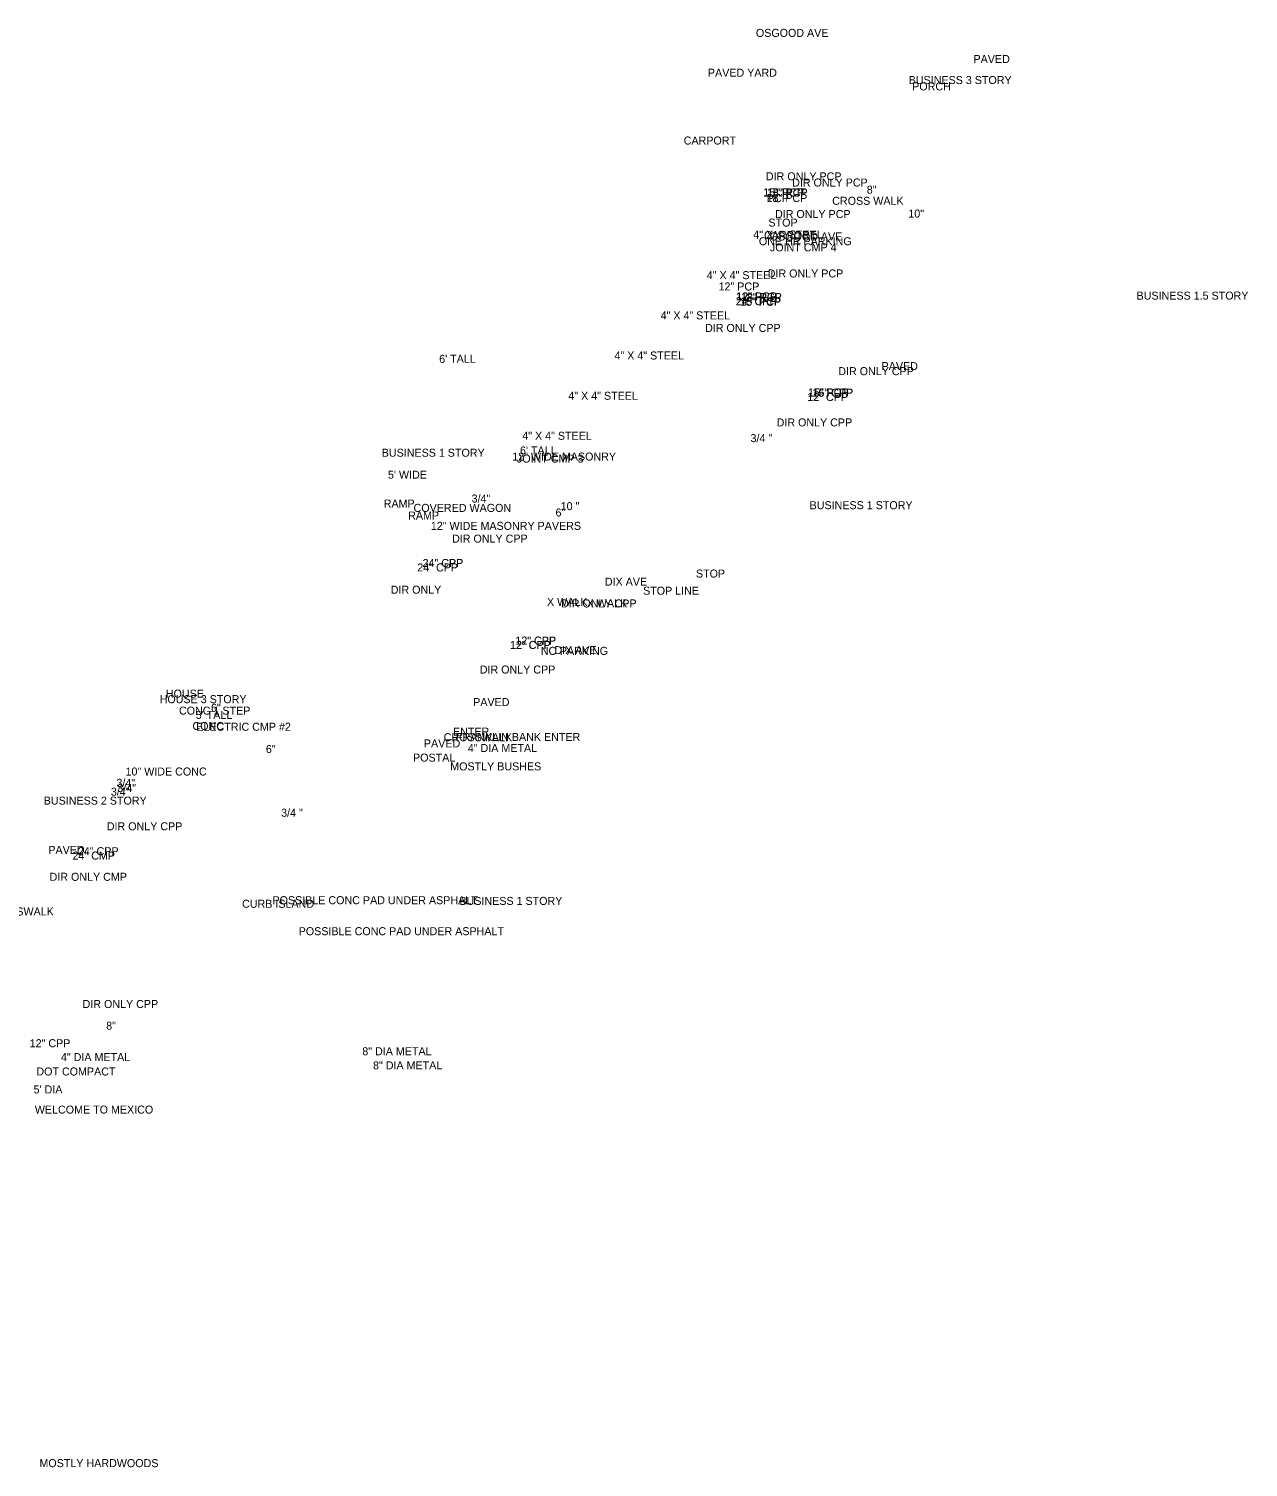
# Model space of a CAD drawing. Extents: x 939002 to 940105, y 627262 to 628202.
# Drawn here: x 939724.4 to 940105, y 627752.3 to 628201.6 of the extents above; entities that cross this region are included whole.
import ezdxf

# ---------------------------------------------------------------- set-up
doc = ezdxf.new("R2010")
doc.units = 0
for name, color, linetype in [('S_Annotation_Label', 7, 'Continuous'), ('S_Buildings', 7, 'Continuous'), ('S_Buildings_Attachments', 7, 'Continuous'), ('S_Buildings_Canopy_Carport', 7, 'Continuous'), ('S_Buildings_SillElevation', 7, 'Continuous'), ('S_Buildings_Steps_Brick', 7, 'Continuous'), ('S_Drainage_Culvert_Top', 7, 'Continuous'), ('S_Drainage_Invert', 7, 'Continuous'), ('S_Fencing_ChainLink', 7, 'Continuous'), ('S_Fencing_Picket', 7, 'Continuous'), ('S_Ground_LevelString', 7, 'Continuous'), ('S_Property_ConcPad', 7, 'Continuous'), ('S_Property_Mailbox', 7, 'Continuous'), ('S_Property_Walkways', 7, 'Continuous'), ('S_RetWall_Top', 7, 'Continuous'), ('S_Roadway_Centerline', 7, 'Continuous'), ('S_Roadway_Edge_Pavement', 7, 'Continuous'), ('S_Roadway_Sidewalks', 7, 'Continuous'), ('S_Traffic_Post_Conc', 7, 'Continuous'), ('S_Traffic_Sign_DoublePost', 7, 'Continuous'), ('S_Traffic_Sign_SinglePost', 7, 'Continuous'), ('S_Trees_Bush', 7, 'Continuous'), ('S_Trees_Bush_Line', 7, 'Continuous'), ('S_Trees_HedgeLine', 7, 'Continuous'), ('S_Trees_TreeLine', 7, 'Continuous'), ('S_Utilities_Pole_Power', 7, 'Continuous'), ('S_Utilities_UG_Sanitary_Sewer', 7, 'Continuous'), ('S_Utilities_UG_Water_Line', 7, 'Continuous')]:
    doc.layers.add(name, color=color, linetype=linetype)

msp = doc.modelspace()

# ---------------------------------------------------------------- texts
at = {"layer": 'S_Annotation_Label'}
for s, height, p in [('CROSS WALK', 2.5, (939975.16, 628146.58)), ('STOP LINE', 2.5, (939916.12, 628024.81)), ('X WALK', 2.5, (939886.12, 628021.32)), ('X WALK', 2.5, (939898.52, 628020.9)), ('CURB ISLAND', 2.4999, (939790.94, 627927.02)), ('CROSSWALK', 2.5, (939710.81, 627924.62)), ('POSSIBLE CONC PAD UNDER ASPHALT', 2.4999, (939808.61, 627918.46))]:
    msp.add_text(s, height=height, dxfattribs=at).set_placement(p)
at = {"layer": 'S_Buildings'}
msp.add_text('HOUSE', height=2.5, dxfattribs=at).set_placement((939767.14, 627992.66))
at = {"layer": 'S_Buildings_Attachments'}
msp.add_text('RAMP', height=2.5, dxfattribs=at).set_placement((939835.15, 628052.01))
at = {"layer": 'S_Buildings_Canopy_Carport'}
for p in [(939928.8, 628165.41), (939953.88, 628135.87)]:
    msp.add_text('CARPORT', height=2.5, dxfattribs=at).set_placement(p)
at = {"layer": 'S_Buildings_SillElevation'}
for s, height, p in [('BUSINESS 3 STORY', 2.4999, (939999.04, 628184.3)), ('PORCH', 2.5, (940000.13, 628182.31)), ('BUSINESS 1.5 STORY', 2.4999, (940070.18, 628116.97)), ('BUSINESS 1 STORY', 2.4999, (939834.54, 628067.9)), ('BUSINESS 1 STORY', 2.4999, (939968.11, 628051.52)), ('HOUSE 3 STORY', 2.4999, (939765.21, 627990.93)), ('BUSINESS 2 STORY', 2.4999, (939729.03, 627959.24)), ('BUSINESS 1 STORY', 2.4999, (939858.79, 627927.92))]:
    msp.add_text(s, height=height, dxfattribs=at).set_placement(p)
at = {"layer": 'S_Buildings_Steps_Brick'}
msp.add_text('CONC 1 STEP', height=2.4999, dxfattribs=at).set_placement((939771.24, 627987.35))
at = {"layer": 'S_Drainage_Culvert_Top'}
for s, height, p in [('DIR ONLY PCP', 2.4999, (939954.46, 628154.23)), ('DIR ONLY PCP', 2.4999, (939962.65, 628152.3)), ('15" PCP', 2.5, (939953.63, 628149.22)), ('PCP', 2.5, (939954.76, 628147.41)), ('18" PCP', 2.5, (939954.78, 628149.2)), ('DIR ONLY PCP', 2.4999, (939957.3, 628142.45)), ('DIR ONLY PCP', 2.4999, (939955.03, 628123.89)), ('12" PCP', 2.5, (939939.69, 628119.82)), ('24" CPP', 2.5, (939945.08, 628115.26)), ('12" PCP', 2.5, (939945.15, 628116.74)), ('15" PCP', 2.5, (939946.41, 628115.04)), ('18" PCP', 2.5, (939946.68, 628116.53)), ('DIR ONLY CPP', 2.4999, (939935.47, 628106.87)), ('DIR ONLY CPP', 2.4999, (939977.06, 628093.38)), ('15" PCP', 2.5, (939967.56, 628086.7)), ('12" CPP', 2.5, (939967.36, 628085.3)), ('15" CPP', 2.5, (939968.99, 628086.63)), ('DIR ONLY CPP', 2.4999, (939957.81, 628077.37)), ('DIR ONLY CPP', 2.4999, (939856.49, 628041.07)), ('24" CPP', 2.5, (939847.26, 628033.44)), ('DIR ONLY', 2.5, (939837.34, 628025.12)), ('DIR ONLY CPP', 2.4999, (939890.5, 628020.83)), ('12" CPP', 2.5, (939874.55, 628007.85)), ('12" CPP', 2.5, (939876.25, 628009.2)), ('DIR ONLY CPP', 2.4999, (939865.13, 628000.19)), ('DIR ONLY CPP', 2.4999, (939748.7, 627951.22)), ('24" CPP', 2.5, (939739.68, 627943.44)), ('24" CMP', 2.5, (939738, 627942.05)), ('DIR ONLY CMP', 2.4999, (939730.85, 627935.45)), ('DIR ONLY CPP', 2.4999, (939741.15, 627895.72)), ('12" CPP', 2.5, (939724.64, 627883.46))]:
    msp.add_text(s, height=height, dxfattribs=at).set_placement(p)
at = {"layer": 'S_Drainage_Invert'}
for s, p in [('15" PCP', (939953.64, 628149.17)), ('18" PCP', (939954.68, 628147.44)), ('18" PCP', (939954.8, 628149.12)), ('12" PCP', (939939.67, 628119.82)), ('24" CPP', (939945.07, 628115.22)), ('12" PCP', (939945.25, 628116.71)), ('15" PCP', (939946.51, 628115.17)), ('18" PCP', (939946.71, 628116.53)), ('15" PCP', (939967.6, 628086.75)), ('15" CPP', (939969.02, 628086.67)), ('12" CPP', (939967.38, 628085.28)), ('24" CPP', (939847.29, 628033.47)), ('24" CPP', (939845.63, 628032.07)), ('12" CPP', (939874.63, 628007.88)), ('12" CPP', (939876.27, 628009.24)), ('24" CPP', (939739.67, 627943.44)), ('24" CMP', (939738.01, 627942.08)), ('12" CPP', (939724.62, 627883.48))]:
    msp.add_text(s, height=2.5, dxfattribs=at).set_placement(p)
at = {"layer": 'S_Fencing_ChainLink'}
for p in [(939852.46, 628097.23), (939877.7, 628068.61)]:
    msp.add_text("6' TALL", height=2.5, dxfattribs=at).set_placement(p)
at = {"layer": 'S_Fencing_Picket'}
msp.add_text("5' TALL", height=2.5, dxfattribs=at).set_placement((939776.47, 627986.01))
at = {"layer": 'S_Ground_LevelString'}
msp.add_text('POSSIBLE CONC PAD UNDER ASPHALT', height=2.4999, dxfattribs=at).set_placement((939800.42, 627928.14))
at = {"layer": 'S_Property_ConcPad'}
msp.add_text('RAMP', height=2.5, dxfattribs=at).set_placement((939842.78, 628048.29))
at = {"layer": 'S_Property_Mailbox'}
msp.add_text('POSTAL', height=2.5, dxfattribs=at).set_placement((939844.31, 627972.67))
at = {"layer": 'S_Property_Walkways'}
msp.add_text('CONC', height=2.5, dxfattribs=at).set_placement((939775.45, 627982.54))
at = {"layer": 'S_RetWall_Top'}
for s, p in [('12" WIDE MASONRY', (939875.28, 628066.7)), ('12" WIDE MASONRY PAVERS', (939849.87, 628045.06)), ('10" WIDE CONC', (939754.55, 627968.33))]:
    msp.add_text(s, height=2.4999, dxfattribs=at).set_placement(p)
at = {"layer": 'S_Roadway_Centerline'}
for s, p in [('OSGOOD AVE', (939951.33, 628199.03)), ('DIX AVE', (939904.19, 628027.62))]:
    msp.add_text(s, height=2.5, dxfattribs=at).set_placement(p)
at = {"layer": 'S_Roadway_Edge_Pavement'}
msp.add_text('PAVED YARD', height=2.5, dxfattribs=at).set_placement((939936.36, 628186.59))
at = {"layer": 'S_Roadway_Sidewalks'}
for p in [(940019.27, 628190.87), (939990.58, 628094.95), (939863.08, 627990.02), (939847.7, 627977.11), (939730.46, 627943.85)]:
    msp.add_text('PAVED', height=2.5, dxfattribs=at).set_placement(p)
at = {"layer": 'S_Traffic_Post_Conc'}
for s, p in [('4" X 4" STEEL', (939950.53, 628136.05)), ('4" X 4" STEEL', (939936, 628123.36)), ('4" X 4" STEEL', (939921.59, 628110.79)), ('4" X 4" STEEL', (939907.19, 628098.27)), ('4" X 4" STEEL', (939892.8, 628085.69)), ('4" X 4" STEEL', (939878.42, 628073.19)), ('4" DIA METAL', (939861.41, 627975.67)), ('8" DIA METAL', (939828.47, 627880.96)), ('4" DIA METAL', (939734.39, 627879.13)), ('8" DIA METAL', (939831.82, 627876.55))]:
    msp.add_text(s, height=2.4999, dxfattribs=at).set_placement(p)
at = {"layer": 'S_Traffic_Sign_DoublePost'}
msp.add_text('WELCOME TO MEXICO', height=2.4999, dxfattribs=at).set_placement((939726.24, 627862.74))
at = {"layer": 'S_Traffic_Sign_SinglePost'}
for s, height, p in [('STOP', 2.5, (939955.26, 628139.78)), ('ONE HR PARKING', 2.4999, (939952.27, 628133.95)), ('OSGOOD AVE', 2.5, (939955.65, 628135.44)), ('COVERED WAGON', 2.4999, (939844.47, 628050.67)), ('STOP', 2.5, (939932.62, 628030.16)), ('NO PARKING', 2.5, (939884.2, 628006.01)), ('DIX AVE', 2.5, (939888.44, 628006.24)), ('CROSSWALK', 2.5, (939853.88, 627979.04)), ('ENTER', 2.5, (939856.77, 627980.79)), ('FRANKLIN BANK ENTER', 2.4999, (939857.7, 627979.12)), ('DOT COMPACT', 2.4999, (939726.72, 627874.64))]:
    msp.add_text(s, height=height, dxfattribs=at).set_placement(p)
at = {"layer": 'S_Trees_Bush'}
msp.add_text("5' DIA", height=2.5, dxfattribs=at).set_placement((939725.86, 627869.04))
at = {"layer": 'S_Trees_Bush_Line'}
msp.add_text('MOSTLY BUSHES', height=2.4999, dxfattribs=at).set_placement((939855.91, 627969.94))
at = {"layer": 'S_Trees_HedgeLine'}
msp.add_text("5' WIDE", height=2.5, dxfattribs=at).set_placement((939836.48, 628061.04))
at = {"layer": 'S_Trees_TreeLine'}
msp.add_text('MOSTLY HARDWOODS', height=2.4999, dxfattribs=at).set_placement((939727.68, 627752.32))
at = {"layer": 'S_Utilities_Pole_Power'}
for s, p in [('JOINT CMP 4', (939955.72, 628132.04)), ('JOINT CMP 3', (939876.74, 628066.06)), ('ELECTRIC CMP #2', (939776.64, 627982.31))]:
    msp.add_text(s, height=2.4999, dxfattribs=at).set_placement(p)
at = {"layer": 'S_Utilities_UG_Sanitary_Sewer'}
msp.add_text('8"', height=2.5, dxfattribs=at).set_placement((939748.52, 627888.95))
at = {"layer": 'S_Utilities_UG_Water_Line'}
for s, p in [('8"', (939985.94, 628150.06)), ('10"', (939998.93, 628142.6)), ('3/4 "', (939949.66, 628072.46)), ('3/4"', (939862.59, 628053.6)), ('10 "', (939890.4, 628051.22)), ('6"', (939888.78, 628049.22)), ('6"', (939781.23, 627988.24)), ('6"', (939798.37, 627975.34)), ('3/4"', (939749.97, 627962.03)), ('3/4"', (939751.72, 627964.78)), ('3/4"', (939751.99, 627963.18)), ('3/4 "', (939803.14, 627955.46))]:
    msp.add_text(s, height=2.5, dxfattribs=at).set_placement(p)

doc.saveas('drawing.dxf')
